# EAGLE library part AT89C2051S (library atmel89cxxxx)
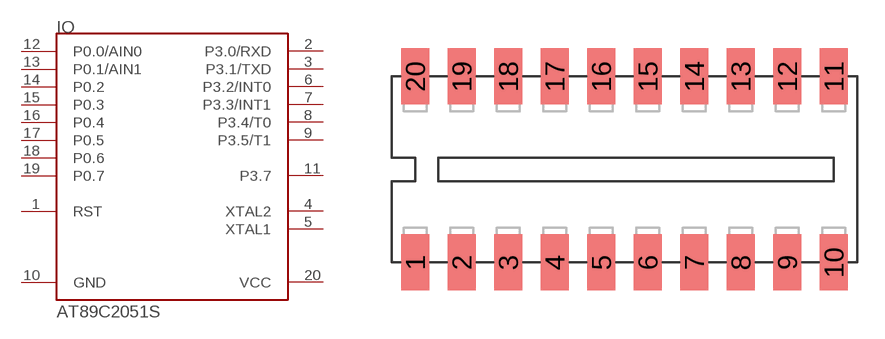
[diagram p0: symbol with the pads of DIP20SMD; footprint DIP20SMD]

Designator prefix IO

## AT89C2051S  [DIP20SMD]
1  RST  pwr
2  P3.0/RXD
3  P3.1/TXD
4  XTAL2  pwr
5  XTAL1  pwr
6  P3.2/INT0
7  P3.3/INT1
8  P3.4/T0
9  P3.5/T1
10  GND  pwr
11  P3.7
12  P0.0/AIN0
13  P0.1/AIN1
14  P0.2
15  P0.3
16  P0.4
17  P0.5
18  P0.6
19  P0.7
20  VCC  pwr

## Footprint DIP20SMD (pad centres in mm)
smd 1.524 x 3.048: 1 -11.43,-5.08; 2 -8.89,-5.08; 3 -6.35,-5.08; 4 -3.81,-5.08; 5 -1.27,-5.08; 6 1.27,-5.08; 7 3.81,-5.08; 8 6.35,-5.08; 9 8.89,-5.08; 10 11.43,-5.08; 11 11.43,5.08; 12 8.89,5.08; 13 6.35,5.08; 14 3.81,5.08; 15 1.27,5.08; 16 -1.27,5.08; 17 -3.81,5.08; 18 -6.35,5.08; 19 -8.89,5.08; 20 -11.43,5.08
